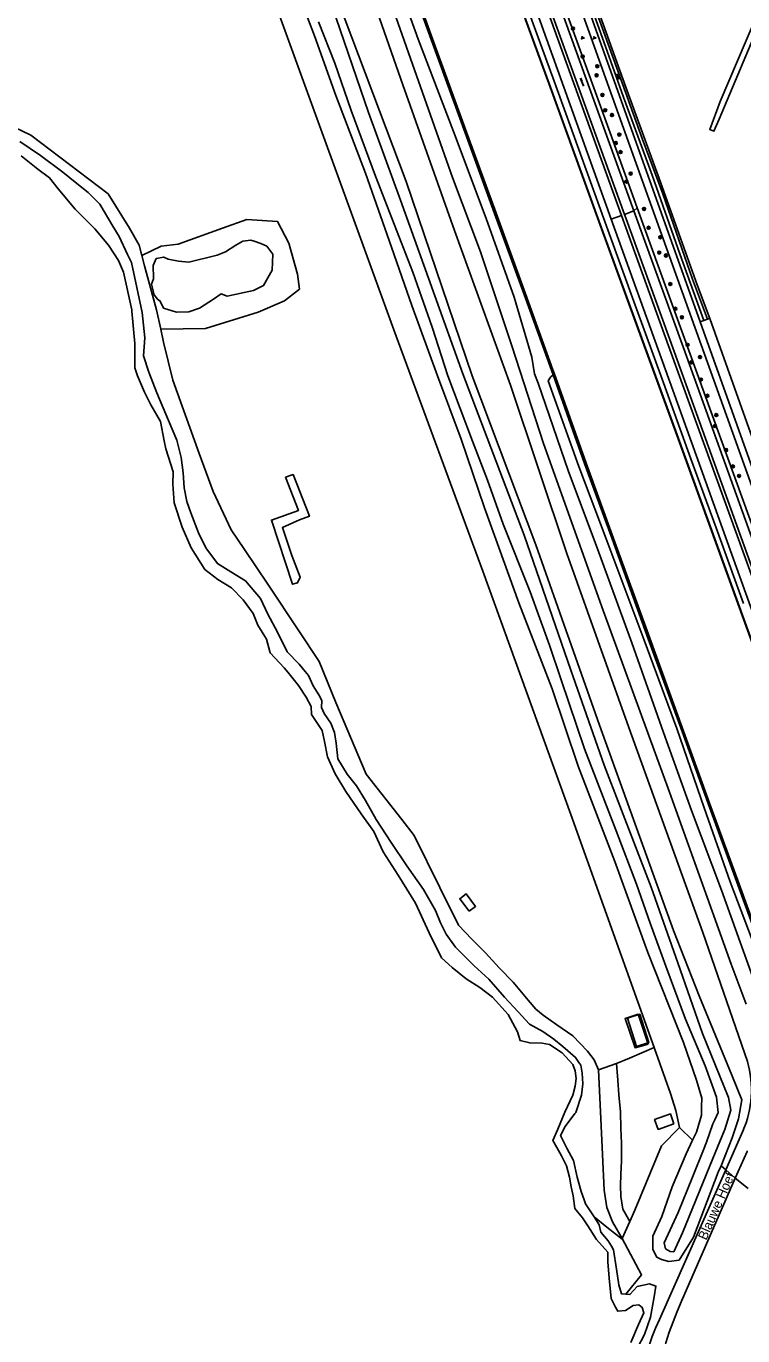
# Model space of a CAD drawing. Extents: x 135990 to 139000, y 393500 to 396000.
# Drawn here: x 136344.8 to 136534.3, y 394644.4 to 394991 of the extents above; entities that cross this region are included whole.
import ezdxf

# ---------------------------------------------------------------- set-up
doc = ezdxf.new("R2010")
doc.units = 0
for name, color, linetype in [('gg-anno-openbare ruimte label', 7, 'Continuous'), ('gg-bbg-luifel en loopbrug', 7, 'Continuous'), ('gg-bbg-overig bouwwerk', 7, 'Continuous'), ('gg-knt-BGT kruinlijn', 7, 'Continuous'), ('gg-knt-onverhard', 7, 'Continuous'), ('gg-knt-verharding', 7, 'Continuous'), ('gg-kntw-beschoeiing', 7, 'Continuous'), ('gg-kntw-bovenkant insteek waterloop', 7, 'Continuous'), ('gt-grn-groengrens', 7, 'Continuous'), ('gt-grn-vlakafsluiter', 7, 'Continuous'), ('gt-grn-weggrens', 7, 'Continuous'), ('gt-symb-boom', 7, 'Continuous'), ('gt-symb-groenvak', 7, 'Continuous'), ('gt-symb-tegel verharding', 7, 'Continuous'), ('gt-symb-watersymbool', 7, 'Continuous'), ('gx-grn-maaiveld', 7, 'Continuous')]:
    doc.layers.add(name, color=color, linetype=linetype)

# ---------------------------------------------------------------- blocks, each defined once
blk = doc.blocks.new('gt0-BOOM')
at = {"layer": 'gt-symb-boom'}
for radius in [0.4, 0.2]:
    blk.add_circle((0, 0), radius, dxfattribs=at)
blk = doc.blocks.new('gt0-WA')
at = {"layer": 'gt-symb-watersymbool'}
for centre, start, end in [((-0.32, 0.02), 28.0725, 151.9275), ((0.43, 0.42), 208.0725, 331.9275), ((-0.32, -0.43), 28.0725, 151.9275), ((0.43, -0.03), 208.0725, 331.9275)]:
    blk.add_arc(centre, 0.425, start, end, dxfattribs=at)
blk = doc.blocks.new('gt0-TEG1')
at = {"layer": 'gt-symb-tegel verharding'}
for p, q in [((-1.12, 0), (1.12, 0)), ((-0.9, -0.25), (-0.9, 0.25)), ((-0.45, -0.25), (-0.45, 0.25)), ((0, -0.25), (0, 0.25)), ((0.45, -0.25), (0.45, 0.25)), ((0.9, -0.25), (0.9, 0.25))]:
    blk.add_line(p, q, dxfattribs=at)
blk = doc.blocks.new('gt0-GRVAK')
at = {"layer": 'gt-symb-groenvak'}
for p, q in [((-0.11, 0.19), (-0.23, 0.24)), ((-0.18, 0.15), (0.09, 0.15)), ((-0.09, 0.21), (-0.16, 0.32)), ((-0.05, 0.21), (-0.05, 0.39)), ((0, 0.21), (0.06, 0.32)), ((0.01, 0.19), (0.13, 0.24)), ((0.26, -0.05), (0.2, 0.06)), ((0.3, -0.05), (0.3, 0.13)), ((0.35, -0.05), (0.41, 0.06)), ((-0.25, -0.23), (-0.36, -0.18)), ((-0.32, -0.26), (-0.05, -0.26)), ((-0.23, -0.21), (-0.29, -0.09)), ((-0.18, -0.2), (-0.18, -0.02)), ((-0.14, -0.21), (-0.07, -0.09)), ((-0.12, -0.23), (0, -0.18)), ((0.24, -0.07), (0.12, -0.02)), ((0.17, -0.11), (0.44, -0.11)), ((0.37, -0.07), (0.49, -0.02))]:
    blk.add_line(p, q, dxfattribs=at)

msp = doc.modelspace()

# ---------------------------------------------------------------- linework, layer by layer
at = {"layer": 'gg-bbg-luifel en loopbrug'}
msp.add_lwpolyline([(136506.22, 394720.948), (136509.492, 394722.016), (136507.039, 394729.527), (136503.768, 394728.458), (136506.22, 394720.948)], dxfattribs=at)
at = {"layer": 'gg-bbg-overig bouwwerk'}
for points in [[(136461.901, 394756.768), (136463.631, 394758.051), (136461.169, 394761.372), (136459.439, 394760.089), (136461.901, 394756.768)], [(136516.099, 394700.566), (136511.936, 394699.047), (136510.987, 394701.646), (136515.15, 394703.165), (136516.099, 394700.566)]]:
    msp.add_lwpolyline(points, dxfattribs=at)
at = {"layer": 'gg-knt-BGT kruinlijn'}
for p, q in [((136484.41, 394976.401), (136477.493, 394995.225)), ((136491.754, 394956.101), (136484.41, 394976.401)), ((136498.62, 394937.093), (136491.754, 394956.101)), ((136505.867, 394917.157), (136498.62, 394937.093)), ((136513.31, 394896.596), (136505.867, 394917.157)), ((136520.581, 394876.443), (136513.31, 394896.596)), ((136527.253, 394858.185), (136520.581, 394876.443)), ((136534.507, 394838.207), (136527.253, 394858.185))]:
    msp.add_line(p, q, dxfattribs=at)
at = {"layer": 'gg-knt-onverhard'}
for points in [[(136502.227, 394940.891), (136445.991, 395096.927), (136442.266, 395108.523)], [(136439.383, 395107.489), (136465.254, 395035.404), (136499.524, 394939.915)], [(136499.524, 394939.915), (136515.762, 394894.671), (136568.749, 394747.032), (136620.794, 394602.897), (136692.782, 394404.289), (136755.093, 394233.967), (136784.32, 394158.437), (136812.069, 394081.979), (136846.919, 393985.953)], [(136850.573, 393987.265), (136825.748, 394055.469), (136794.632, 394141.703), (136779.568, 394182.176), (136771.571, 394200.994), (136765.12, 394216.82), (136761.177, 394227.254), (136756.235, 394240.594), (136752.111, 394252.251), (136738.863, 394288.188), (136717.12, 394347.822), (136703.382, 394385.806), (136687.311, 394429.828), (136675.881, 394461.138), (136656.833, 394513.719), (136646.439, 394542.225), (136618.639, 394619.052), (136585.19, 394711.492), (136513.528, 394909.534), (136502.227, 394940.891)]]:
    msp.add_lwpolyline(points, dxfattribs=at)
at = {"layer": 'gg-knt-verharding'}
for p, q in [((136481.776, 395000), (136503.014, 394941.175)), ((136484.606, 395000), (136505.512, 394942.077)), ((136499.22, 394962.743), (136485.76, 395000)), ((136502.742, 394964.003), (136489.86, 395000)), ((136668.79, 394500), (136502.742, 394964.003)), ((136506.374, 394942.942), (136499.22, 394962.743)), ((136569.294, 394768.782), (136506.374, 394942.942)), ((136503.014, 394941.175), (136503.442, 394939.989))]:
    msp.add_line(p, q, dxfattribs=at)
for points in [[(136503.442, 394939.989), (136516.118, 394904.881), (136566.227, 394765.796)], [(136505.512, 394942.077), (136518.6, 394905.816), (136568.296, 394767.811)]]:
    msp.add_lwpolyline(points, dxfattribs=at)
at = {"layer": 'gg-kntw-beschoeiing'}
for p, q in [((136445.31, 395006.266), (136451.707, 394988.509)), ((136451.707, 394988.509), (136460.716, 394963.79)), ((136460.716, 394963.79), (136468.839, 394941.452)), ((136468.839, 394941.452), (136476.659, 394920.044)), ((136476.659, 394920.044), (136483.876, 394899.972)), ((136483.876, 394899.972), (136484.212, 394899.067)), ((136484.212, 394899.067), (136492.651, 394875.279)), ((136499.947, 394855.367), (136509.494, 394828.96)), ((136509.494, 394828.96), (136518.115, 394805.364)), ((136518.115, 394805.364), (136525.647, 394784.372)), ((136525.647, 394784.372), (136533.159, 394763.839)), ((136533.159, 394763.839), (136545.233, 394730.646))]:
    msp.add_line(p, q, dxfattribs=at)
at = {"layer": 'gg-kntw-bovenkant insteek waterloop'}
for p, q in [((136491.92, 395000), (136523.02, 394912.745)), ((136525.584, 394913.655), (136540.027, 394872.959))]:
    msp.add_line(p, q, dxfattribs=at)
for points in [[(136543.563, 395003.296), (136528.045, 394966.394), (136526.677, 394963.141), (136525.553, 394963.614), (136528.301, 394971.008), (136542.325, 395004.007)], [(136523.02, 394912.745), (136554.12, 394825.49), (136615.21, 394658.072), (136661.88, 394543.88), (136670.581, 394520.988), (136678.884, 394500)]]:
    msp.add_lwpolyline(points, dxfattribs=at)
at = {"layer": 'gt-grn-groengrens'}
msp.add_line((136506.374, 394942.942), (136505.512, 394942.077), dxfattribs=at)
at = {"layer": 'gt-grn-vlakafsluiter'}
for p, q in [((136523.02, 394912.745), (136523.981, 394913.086)), ((136523.981, 394913.086), (136524.943, 394913.427)), ((136524.943, 394913.427), (136525.584, 394913.655))]:
    msp.add_line(p, q, dxfattribs=at)
at = {"layer": 'gt-grn-weggrens'}
for p, q in [((136502.227, 394940.891), (136499.524, 394939.915)), ((136505.512, 394942.077), (136503.014, 394941.175))]:
    msp.add_line(p, q, dxfattribs=at)
at = {"layer": 'gx-grn-maaiveld'}
for p, q in [((136375.383, 394930.257), (136376.072, 394927.558)), ((136379.256, 394915.937), (136376.072, 394927.558)), ((136380.354, 394910.828), (136379.256, 394915.937)), ((136496.122, 394714.778), (136500.91, 394716.519)), ((136517.516, 394699.545), (136512.815, 394694.718)), ((136517.516, 394699.545), (136521.028, 394696.175)), ((136528.579, 394689.452), (136529.776, 394688.386)), ((136529.776, 394688.386), (136512.235, 394648.733)), ((136532.327, 394686.115), (136518.11, 394653.594)), ((136529.776, 394688.386), (136532.327, 394686.115)), ((136535.757, 394683.457), (136532.327, 394686.115)), ((136502.42, 394670.148), (136504.424, 394674.717))]:
    msp.add_line(p, q, dxfattribs=at)
for points in [[(136535.526, 394716.997), (136523.691, 394751.132), (136504.129, 394805.416), (136487.721, 394851.459), (136472.886, 394895.957), (136458.069, 394936.914), (136444.349, 394975.425), (136432.215, 395010.308), (136417.121, 395052.784), (136405.905, 395088.093), (136394.317, 395123.396), (136390.543, 395133.48), (136380.105, 395158.728), (136367.012, 395190.453), (136365.986, 395191.971), (136364.861, 395193.033), (136363.424, 395193.94), (136361.886, 395194.368), (136360.72, 395194.424), (136359.309, 395194.255), (136358.279, 395193.667), (136357.467, 395192.765), (136354.939, 395188.859), (136353.855, 395187.184)], [(136387.443, 395119.616), (136394.929, 395100.464), (136403.88, 395071.705), (136408.997, 395054.919), (136425.633, 395002.075), (136445.291, 394949.88), (136462.725, 394898.443), (136479.587, 394853.693), (136496.379, 394806.026), (136515.946, 394751.704), (136522.737, 394734.37), (136531.412, 394713.4), (136534.056, 394706.843), (136533.204, 394701.819), (136531.532, 394696.797), (136528.579, 394689.452)], [(136451.823, 395120.311), (136451.986, 395119.358), (136452.59, 395117.838), (136453.181, 395115.541), (136454.03, 395113.231), (136453.871, 395112.381), (136459.474, 395097.431), (136465.475, 395080.091), (136472.14, 395060.999), (136478.407, 395043.978), (136484.435, 395027.355), (136492.189, 395004.306), (136500.102, 394982.319), (136507.643, 394961.235), (136513.113, 394946.604), (136521.026, 394924.033), (136524.943, 394913.427)], [(136452.283, 395121.15), (136453.221, 395118.034), (136454.548, 395113.387), (136454.442, 395112.192), (136459.886, 395097.826), (136466.232, 395079.504), (136474.278, 395057.172), (136484.183, 395030.113), (136492.972, 395003.825), (136503.328, 394974.801), (136512.569, 394949.681), (136522.208, 394922.543), (136525.584, 394913.655)], [(136441.873, 395089.213), (136447.07, 395074.856), (136455.748, 395050.928), (136464.393, 395026.965), (136473.246, 395002.595), (136483.334, 394974.818), (136495.897, 394940.257), (136506.179, 394911.979), (136516.812, 394882.757), (136527.535, 394853.32), (136537.393, 394826.074), (136548.777, 394794.872), (136558.736, 394767.499), (136567.132, 394744.17)], [(136441.967, 395089.248), (136447.164, 395074.89), (136455.842, 395050.962), (136464.487, 395026.999), (136473.34, 395002.629), (136483.428, 394974.852), (136495.991, 394940.291), (136506.273, 394912.013), (136516.906, 394882.791), (136527.629, 394853.354), (136537.487, 394826.108), (136548.871, 394794.906), (136558.83, 394767.533), (136567.226, 394744.205)], [(136413.121, 395078.981), (136417.421, 395065.386), (136427.044, 395036.953), (136437.19, 395008.792), (136446.982, 394980.89), (136457.504, 394950.918), (136464.932, 394931.251), (136473.203, 394906.343), (136481.552, 394880.553), (136497.334, 394836.338), (136514.886, 394788.243), (136531.246, 394742.795), (136535.211, 394732.218)], [(136421.65, 395070.86), (136427.514, 395054.664), (136436.772, 395029.308), (136445.122, 395006.198), (136451.519, 394988.441), (136460.528, 394963.722), (136468.651, 394941.384), (136476.471, 394919.976), (136483.688, 394899.904), (136483.759, 394899.713), (136484.119, 394898.73)], [(136422.026, 395070.996), (136427.89, 395054.8), (136437.148, 395029.444), (136445.498, 395006.334), (136451.895, 394988.577), (136460.904, 394963.858), (136469.027, 394941.52), (136476.847, 394920.112), (136484.064, 394900.04), (136484.4, 394899.135), (136492.839, 394875.347), (136500.135, 394855.435), (136509.682, 394829.028), (136518.303, 394805.432), (136525.835, 394784.44), (136533.347, 394763.907), (136545.421, 394730.714)], [(136420.019, 395070.244), (136425.72, 395054.005), (136434.693, 395028.68), (136441.954, 395005.67), (136448.462, 394987.524), (136457.776, 394963.065), (136466.412, 394940.091), (136473.868, 394919.238), (136478.511, 394903.352), (136479.217, 394898.954), (136480.134, 394896.532), (136488.214, 394873.15), (136495.537, 394853.669), (136504.915, 394827.812), (136513.321, 394804.1), (136520.76, 394783.468), (136528.662, 394762.332), (136540.602, 394729.153)], [(136510.827, 394720.725), (136488.806, 394782.383), (136465.504, 394846.75), (136442.035, 394910.646), (136408.245, 395003.617), (136390.925, 395050.665), (136381.267, 395048.401), (136344.544, 395015.242), (136333.28, 395000.854)], [(136521.028, 394696.175), (136522.032, 394698.287), (136523.391, 394702.854), (136523.416, 394705.071), (136523.441, 394707.288), (136522.064, 394712.072), (136518.606, 394722.09), (136509.226, 394745.826), (136500.438, 394769.902), (136490.751, 394795.205), (136483.862, 394815.649), (136475.021, 394838.358), (136466.001, 394863.494), (136459.775, 394881.732), (136453.529, 394898.444), (136446.784, 394917.052), (136440.775, 394934.297), (136434.476, 394952.039), (136426.687, 394972.595), (136420.989, 394988.42), (136414.786, 395004.944)], [(136523.981, 394913.086), (136517.76, 394930.472), (136510.299, 394951.53), (136502.757, 394972.162), (136497.951, 394985.572), (136491.18, 395004.665)], [(136425.655, 394996.14), (136435.261, 394968.114), (136443.751, 394944.935), (136460.256, 394898.989), (136476.515, 394856.26), (136488.801, 394820.558), (136497.651, 394795.414), (136510.05, 394763.178), (136517.125, 394743.14), (136523.636, 394724.389), (136530.517, 394707.48), (136531.103, 394704.11), (136529.52, 394699.028), (136529.458, 394698.83), (136526.418, 394691.376), (136518.374, 394671.649), (136516.026, 394666.687), (136515.091, 394666.732), (136513.853, 394667.483), (136513.475, 394669.035), (136517.246, 394677.038), (136520.955, 394686.414), (136523.884, 394693.632), (136524.712, 394695.671), (136526.401, 394700.57), (136526.896, 394701.626), (136527.771, 394703.496), (136527.304, 394707.557), (136524.383, 394715.835), (136519.127, 394728.199), (136513.966, 394742.214), (136509.798, 394753.616), (136506.171, 394763.968), (136500.836, 394778.042), (136492.407, 394799.788), (136486.279, 394817.977), (136483.189, 394827.18), (136478.046, 394841.295), (136470.945, 394859.172), (136466.762, 394870.848), (136462.804, 394881.149), (136456.288, 394898.469), (136452.122, 394911.367), (136447.02, 394925.881), (136437.118, 394951.289), (136430.748, 394968.652), (136426.407, 394981.191), (136422.062, 394992.127)], [(136375.383, 394930.257), (136374.675, 394933.029), (136372.103, 394937.552), (136366.427, 394946.643), (136346.028, 394962.12), (136341.549, 394964.249), (136337.646, 394966.2), (136320.884, 394969.038), (136319.629, 394970.61)], [(136343.057, 394960.435), (136348.511, 394956.754), (136354.453, 394952.364), (136358.134, 394949.326), (136361.194, 394946.976), (136364.254, 394943.827), (136367.669, 394938.062), (136369.309, 394935.313), (136371.527, 394930.524), (136372.635, 394928.439), (136375.461, 394915.168), (136375.618, 394913.56), (136376.173, 394908.506), (136375.828, 394903.77), (136377.156, 394899.448), (136379.354, 394893.93), (136382.391, 394886.636), (136384.586, 394881.455), (136385.784, 394876.843), (136386.316, 394872.807), (136386.582, 394868.816), (136387.247, 394865.18), (136388.267, 394862.164), (136390.351, 394856.887), (136392.258, 394852.896), (136395.318, 394848.772), (136398.91, 394846.555), (136402.724, 394844.16), (136406.715, 394839.548), (136408.711, 394835.424), (136411.238, 394830.634), (136413.81, 394825.446), (136417.003, 394822.164), (136418.555, 394820.213), (136419.398, 394819.193), (136420.64, 394816.444), (136422.192, 394814.005), (136422.99, 394812.497), (136422.901, 394810.679), (136423.567, 394809.082), (136425.34, 394806.51), (136426.316, 394804.071), (136426.759, 394801.233), (136427.228, 394797.106), (136429.619, 394793.057), (136432.17, 394789.925), (136434.514, 394786.077), (136437.334, 394781.025), (136441.261, 394774.936), (136445.473, 394768.772), (136449.819, 394762.519), (136453.012, 394756.932), (136454.343, 394753.739), (136455.806, 394750.723), (136458.289, 394747.308), (136463.256, 394742.342), (136467.114, 394738.794), (136471.238, 394734.049), (136474.919, 394730.191), (136477.846, 394726.865), (136481.394, 394724.914), (136484.32, 394722.963), (136486.744, 394721.03), (136490.058, 394718.1), (136490.96, 394716.771)], [(136343.463, 394956.684), (136347.877, 394953.164), (136350.93, 394950.847), (136353.184, 394947.933), (136357.755, 394942.544), (136362.958, 394937.354), (136366.525, 394933.052), (136369.174, 394928.932), (136370.519, 394925.907), (136372.686, 394915.927), (136372.693, 394915.539), (136373.471, 394907.014), (136373.485, 394900.576), (136374.175, 394898.447), (136376.089, 394894.155), (136377.743, 394890.796), (136380.304, 394886.358), (136381.264, 394881.256), (136381.696, 394879.154), (136383.599, 394873.029), (136383.577, 394869.756), (136383.942, 394864.824), (136386.031, 394858.378), (136388.409, 394852.895), (136392.001, 394847.233), (136395.456, 394844.588), (136399.106, 394842.343), (136402.137, 394839.14), (136404.753, 394835.581), (136406.032, 394832.433), (136408.319, 394828.742), (136409.289, 394825.192), (136412.962, 394821.15), (136413.976, 394820.056), (136416.783, 394816.471), (136418.787, 394813.456), (136420.17, 394810.987), (136420.224, 394808.822), (136423.011, 394804.593), (136423.641, 394801.697), (136424.444, 394797.601), (136426.506, 394793.17), (136429.295, 394788.43), (136433.335, 394782.544), (136436.675, 394777.872), (136439.211, 394772.506), (136443.132, 394766.347), (136447.748, 394758.882), (136451.317, 394751.038), (136454.628, 394744.433), (136457.432, 394741.905), (136461.147, 394738.863), (136464.742, 394736.627), (136468.122, 394734.082), (136472.278, 394729.459), (136474.754, 394724.91), (136475.386, 394722.561), (136477.957, 394721.933), (136481.26, 394721.848), (136483.136, 394721.474), (136486.507, 394719.315), (136489.315, 394716.23), (136489.943, 394714.578), (136490.201, 394712.532), (136490.002, 394710.499), (136489.343, 394708.115), (136487.209, 394703.597), (136485.415, 394699.118), (136484.051, 394696.134), (136484.28, 394695.717), (136486.381, 394692.041), (136487.637, 394689.442), (136488.471, 394686.406), (136488.879, 394683.83), (136489.464, 394681.515), (136489.901, 394678.091), (136491.947, 394675.666), (136493.304, 394673.527), (136495.567, 394669.923), (136498.583, 394666.566), (136498.565, 394664.041), (136498.918, 394659.676), (136499.498, 394654.291), (136500.653, 394652.043), (136501.231, 394650.919), (136503.279, 394651.092), (136505.305, 394652.43), (136506.81, 394652.601), (136507.661, 394651.96), (136508.123, 394650.494), (136506.717, 394647.413), (136504.666, 394642.68)], [(136380.354, 394910.828), (136392.213, 394910.95), (136406.103, 394915.316), (136413.049, 394918.292), (136417.017, 394921.401), (136416.554, 394925.37), (136414.239, 394933.572), (136411.263, 394939.261), (136403.127, 394939.79), (136396.711, 394937.541), (136384.937, 394933.308), (136380.505, 394932.778), (136375.383, 394930.257)], [(136400.242, 394933.013), (136402.022, 394934.117), (136404.142, 394934.349), (136405.101, 394934.109), (136406.782, 394933.494), (136408.394, 394932.772), (136410.006, 394930.596), (136409.807, 394926.362), (136407.558, 394922.327), (136404.846, 394921.004), (136397.901, 394919.483), (136396.332, 394920.111), (136394.329, 394918.755), (136390.625, 394916.374), (136387.781, 394915.382), (136384.474, 394915.25), (136381.1, 394916.374), (136380.218, 394918.226), (136379.473, 394918.689), (136378.653, 394919.853), (136377.938, 394922.684), (136378.426, 394924.113), (136378.405, 394924.265), (136378.388, 394927.619), (136379.182, 394929.471), (136381.166, 394929.868), (136382.291, 394929.273), (136385.003, 394928.81), (136387.764, 394928.495), (136395.268, 394930.412), (136397.471, 394931.253), (136400.242, 394933.013)], [(136496.122, 394714.778), (136495.03, 394717.464), (136493.212, 394719.748), (136489.309, 394723.783), (136485.141, 394726.71), (136481.504, 394729.282), (136479.598, 394730.878), (136477.513, 394733.229), (136473.522, 394737.974), (136469.841, 394741.832), (136466.249, 394745.779), (136462.613, 394749.371), (136459.065, 394753.096), (136454.187, 394763.029), (136447.358, 394776.776), (136444.077, 394781.034), (136434.675, 394793.007), (136426.693, 394811.987), (136422.214, 394822.852), (136416.892, 394831.011), (136408.644, 394843.295), (136402.524, 394852.519), (136398.977, 394857.708), (136394.187, 394867.818), (136390.551, 394877.929), (136383.577, 394897.326), (136381.105, 394907.331), (136380.354, 394910.828)], [(136543.827, 394730.573), (136530.992, 394764.548), (136524.11, 394784.18), (136516.858, 394805.122), (136508.223, 394828.505), (136498.158, 394855.341), (136490.972, 394874.467), (136482.795, 394897.111), (136483.43, 394898.074), (136484.119, 394898.73)], [(136484.119, 394898.73), (136492.463, 394875.211), (136499.759, 394855.299), (136509.306, 394828.892), (136517.927, 394805.296), (136525.459, 394784.304), (136532.971, 394763.771), (136545.045, 394730.578)], [(136413.323, 394871.677), (136415.363, 394872.297), (136419.664, 394861.277), (136417.092, 394860.302), (136412.525, 394858.307), (136415.052, 394850.945), (136417.269, 394845.158), (136416.56, 394843.65), (136415.163, 394843.317), (136409.642, 394860.257), (136416.782, 394862.83), (136413.323, 394871.677)], [(136509.266, 394721.647), (136505.813, 394720.654), (136503.154, 394728.354), (136506.647, 394729.505), (136509.266, 394721.647)], [(136510.827, 394720.725), (136504.365, 394717.896), (136500.91, 394716.519)], [(136510.827, 394720.725), (136510.932, 394720.43), (136515.197, 394708.565), (136516.556, 394704.078), (136517.516, 394699.545)], [(136490.96, 394716.771), (136491.434, 394716.072), (136491.838, 394713.956), (136492.01, 394711.122), (136491.638, 394708.113), (136490.096, 394703.551), (136489.911, 394703.297), (136487.354, 394699.778), (136486.117, 394697.425), (136487.046, 394695.47), (136487.78, 394694.09), (136489.496, 394690.866), (136490.527, 394686.411), (136491.581, 394682.636), (136492.364, 394680.402), (136492.714, 394679.402), (136494.962, 394675.896)], [(136502.42, 394670.148), (136499.797, 394674.637), (136498.378, 394678.362), (136497.669, 394683.018), (136496.782, 394701.865), (136496.122, 394714.778)], [(136500.91, 394716.519), (136501.216, 394712.109), (136501.527, 394708.162), (136501.97, 394703.728), (136502.059, 394699.249), (136502.236, 394695.435), (136502.236, 394690.734), (136502.059, 394687.142), (136501.97, 394684.215), (136502.014, 394681.311), (136502.609, 394677.905), (136504.424, 394674.717)], [(136528.579, 394689.452), (136527.807, 394687.741), (136521.286, 394670.573), (136517.456, 394664.488), (136514.781, 394664.093), (136512.805, 394664.638), (136511.534, 394665.218), (136510.475, 394667.263), (136510.542, 394670.824), (136512.863, 394676.014), (136515.606, 394683.894), (136519.328, 394692.596), (136521.028, 394696.175)], [(136529.776, 394688.386), (136532.972, 394695.61), (136534.302, 394698.616)], [(136512.815, 394694.718), (136505.717, 394677.665), (136504.424, 394674.717)], [(136532.327, 394686.115), (136535.419, 394693.188), (136535.487, 394693.344)], [(136494.962, 394675.896), (136498.332, 394673.162), (136502.434, 394669.987), (136502.42, 394670.148)], [(136494.962, 394675.896), (136496.323, 394673.772), (136496.711, 394671.873), (136498.675, 394669.586), (136499.535, 394668.149), (136500.099, 394667.205), (136500.905, 394662.098), (136501.482, 394657.905), (136502.205, 394655.555), (136503.399, 394655.446)], [(136502.42, 394670.148), (136507.524, 394660.558), (136503.399, 394655.446)], [(136505.679, 394639.728), (136508.315, 394644.752), (136509.888, 394649.347), (136510.859, 394654.786), (136511.338, 394657.587), (136509.645, 394658.193), (136506.374, 394657.494), (136504.448, 394655.351), (136503.399, 394655.446)]]:
    msp.add_lwpolyline(points, dxfattribs=at)
for centre, radius, start, end in [((136509.737, 394709.483), 26.861, 336.13603, 16.24451), ((136592.478, 394619.362), 81.869, 155.28314, 188.09821), ((136572.081, 394620.731), 66.073, 154.92479, 188.8251)]:
    msp.add_arc(centre, radius, start, end, dxfattribs=at)

# ---------------------------------------------------------------- block references
at = {"layer": 'gt-symb-boom'}
for p in [(136489.406, 394990.325), (136491.951, 394982.9), (136495.811, 394980.379), (136495.624, 394977.959), (136497.177, 394972.761), (136497.907, 394968.726), (136499.693, 394967.46), (136500.715, 394960.048), (136501.639, 394962.266), (136501.966, 394957.653), (136503.52, 394949.851), (136504.661, 394951.967), (136508.188, 394942.602), (136509.369, 394937.629), (136512.491, 394935.124), (136512.201, 394931.065), (136513.982, 394930.284), (136515.127, 394922.72), (136516.479, 394916.185), (136518.19, 394913.931), (136519.683, 394906.632), (136520.743, 394902.022), (136522.998, 394903.406), (136523.204, 394897.458), (136524.947, 394893.177), (136527.302, 394888.069), (136526.972, 394885.159), (136529.886, 394878.815), (136531.683, 394874.46), (136533.318, 394871.964)]:
    msp.add_blockref('gt0-BOOM', p, dxfattribs=at)
at = {"layer": 'gt-symb-groenvak'}
for p in [(136491.909, 394987.885), (136495.02, 394987.885)]:
    msp.add_blockref('gt0-GRVAK', p, dxfattribs=at)
at = {"layer": 'gt-symb-tegel verharding', "rotation": -69.02828944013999}
msp.add_blockref('gt0-TEG1', (136491.793, 394976.16), dxfattribs=at)
at = {"layer": 'gt-symb-watersymbool', "rotation": -70.36929772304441}
msp.add_blockref('gt0-WA', (136501.353, 394977.727), dxfattribs=at)

# ---------------------------------------------------------------- texts
at = {"layer": 'gg-anno-openbare ruimte label'}
msp.add_text('Blauwe Hoef', height=2.5, rotation=66.3, dxfattribs=at).set_placement((136524.645, 394669.568))

doc.saveas('drawing.dxf')
